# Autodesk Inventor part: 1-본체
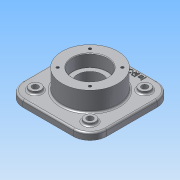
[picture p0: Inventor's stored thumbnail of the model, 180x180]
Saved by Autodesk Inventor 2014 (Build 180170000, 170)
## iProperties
Created: 2015-09
Part Number: 1-본체
Material: 알루미늄 6061
Document SubType Name: Modeling
Designer: study
Mass: 1455.31 g
Surface Area: 796.286 cm^2
Volume: 537.013 cm^3
Density: 2.71 g/cm^3
Appearance: 알루미늄 - 평지
Author: study
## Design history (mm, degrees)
sketch "스케치1"
  geometry: L1 (-75, 75)-(75, 75); L2 (75, 75)-(75, -75); L3 (75, -75)-(-75, -75); L4 (-75, -75)-(-75, 75); L5 (-75, 75)-(75, -75); L6 (75, 75)-(-75, -75); 1 further point
  constraints: 12 end point, 2 midpoint, 2 parallel, 1 horizontal, 1 perpendicular
  dimensions: "d0" = 150 distance of L1.start L1.end; "d1" = 150 distance of L1.end L2.end
extrude "돌출1" new body sketch "스케치1" distance "d2" = 12; taper "d3" = 0 deg
node "작업 평면1"
sketch "스케치2"
  geometry: C1 r 50 at (0, 0); 1 further point
  constraints: 1 centre point, 1 coincident
  dimensions: "d5" = 100 diameter of C1
extrude "돌출2" join sketch "스케치2" distance "d6" = 70; taper "d7" = 0 deg
sketch "스케치3"
  geometry: C1 r 50 at (0, 0) reference; C2 r 10 at (-49, 49); C3 r 10 at (49, 49); C4 r 10 at (-49, -49); C5 r 10 at (49, -49); C6 r 50 at (0, 0) reference
  constraints: 4 centre point, 3 equal radius, 2 horizontal alignment, 2 vertical alignment
  dimensions: "d8" = 20 diameter of C2; "d9" = 98 distance of C5.centre C3.centre; "d10" = 98 distance of C3.centre C2.centre; "d11" = 49 horizontal distance of C1.centre C2.centre; "d12" = 49 horizontal distance of C4.centre C1.centre
extrude "돌출3" join sketch "스케치3" distance "d13" = 5; taper "d14" = 0 deg
sketch "스케치4"
  geometry: C1 r 10 at (0, 0) reference; C2 r 10 at (-98, 0) reference; C3 r 10 at (-98, -98) reference; C4 r 10 at (0, -98) reference; 1 further point
hole "구멍1" sketch "스케치4" at (-98, 0), (0, 0), (0, -98), (-98, -98) diameter "d15" = 11; stored, may be unused: countersink angle "d19" = 90 deg, drill point angle "d21" = 118 deg; dims "d16" = 6, "d17" = 4, "d18" = 2, "d20" = 8
hole "구멍2" diameter "d24" = 45; stored, may be unused: countersink angle "d28" = 90 deg, drill point angle "d30" = 118 deg; dims "d22" = 10, "d23" = 10, "d25" = 6, "d26" = 62, "d27" = 22, "d29" = 8
hole "구멍3" diameter "d33" = 62; stored, may be unused: countersink angle "d37" = 90 deg, drill point angle "d39" = 118 deg; dims "d31" = 10, "d32" = 10, "d34" = 6, "d35" = 62, "d36" = 22, "d38" = 22
sketch "스케치5"
  geometry: L1 (0, 0)-(-41, 0); C1 r 31 at (0, 0) reference; C2 r 50 at (0, 0) reference; A1 r 41 centre (0, 0) between (-28.991, 28.991) and (-41, 0)
  constraints: 2 end point, 2 point on circle, 1 centre point, 1 coincident, 1 horizontal, 1 horizontal alignment
  dimensions: "d40" = 82 diameter of A1; "d42" = 45 deg dimension on C1.centre A1.start L1.end
hole "구멍4" sketch "스케치5" at (-28.991, 28.991) diameter "d43" = 4.917; stored, may be unused: countersink angle "d47" = 90 deg, drill point angle "d49" = 118 deg; dims "d44" = 10, "d45" = 62, "d46" = 22, "d48" = 13
node "작업 평면2"
sketch "스케치6"
  geometry: C1 r 50 at (0, 0) reference; 1 further point
  constraints: 1 vertical alignment, 1 other
  dimensions: "d54" = 65 distance of point (0, 65) C1.centre
feature "엠보싱1" sketch "스케치6" dims "d0" = 150, "d1" = 150, "d55" = 1, "d56" = 0
chamfer "모따기1" distance "d57" = 1; stored, may be unused: second distance "d58" = 2, angle "d59" = 45 deg
fillet "모깎기1" dims "d60" = 30, "d61" = 0.3, "d62" = 3
fillet "모깎기2" dims "d63" = 3
node "솔리드1"
pattern_circular "원형 패턴1" dims angle "d51" = 360 deg
mirror "대칭1"
node "투영된 루프1"
node "투영된 루프2"
node "투영된 루프3"
node "투영된 루프4"
other parameters: "d4" = -23, "d53" = -35
